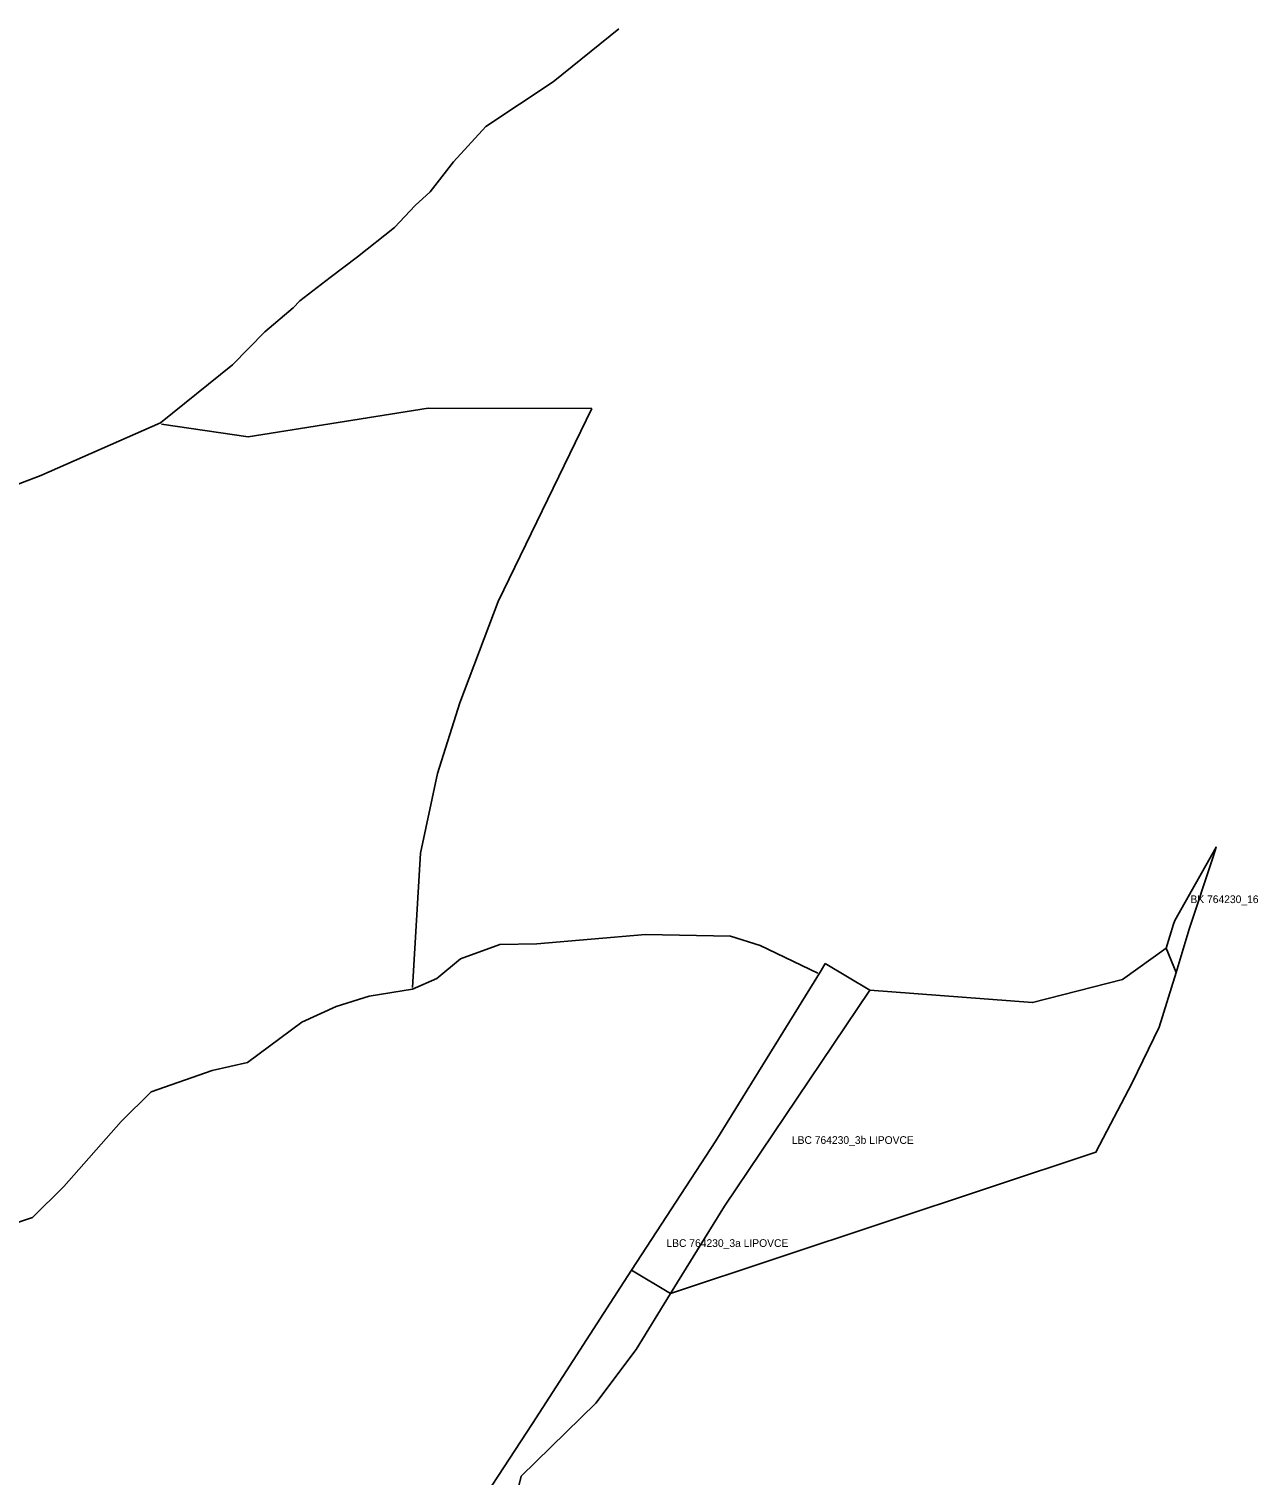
# Model space of a CAD drawing. Extents: x -521616 to -516782, y -1190061 to -1184927.
# Drawn here: x -517900 to -516782, y -1187423 to -1186108 of the extents above; entities that cross this region are included whole.
import ezdxf

# ---------------------------------------------------------------- set-up
doc = ezdxf.new("R2010")
doc.units = 0
for name, color, linetype in [('i_prvek_l_n', 7, 'Continuous'), ('i_prvek_l_s', 7, 'Continuous'), ('LBC_n', 7, 'Continuous'), ('LBC_s', 7, 'Continuous'), ('LBK_s', 7, 'Continuous')]:
    doc.layers.add(name, color=color, linetype=linetype)

msp = doc.modelspace()

# ---------------------------------------------------------------- linework, layer by layer
at = {"layer": 'i_prvek_l_n'}
for points in [[(-517567.3, -1186288.9), (-517548.4, -1186268.9), (-517534.7, -1186256.5), (-517513.6, -1186229.1), (-517484.3, -1186196.9), (-517422.9, -1186156.3), (-517363.2, -1186108.3)], [(-517551, -1186980.2), (-517543.5, -1186858), (-517528.2, -1186785.5), (-517507.7, -1186721.1), (-517472.9, -1186629), (-517387.7, -1186453.4)], [(-517182.2, -1186967.1), (-517234.6, -1186941.8), (-517261.6, -1186933.5), (-517338.9, -1186931.9), (-517437.7, -1186940.4), (-517471.4, -1186941.1)]]:
    msp.add_lwpolyline(points, dxfattribs=at)
at = {"layer": 'i_prvek_l_s'}
for points in [[(-518041.6, -1186572.7), (-517888.9, -1186514.4), (-517779.9, -1186466.6), (-517714.7, -1186413.9), (-517685.2, -1186383.8), (-517659.5, -1186362), (-517653.4, -1186355.5), (-517625.7, -1186334.2), (-517600.9, -1186315.4), (-517567.3, -1186288.9)], [(-517387.7, -1186453.4), (-517536.6, -1186453.3), (-517700.2, -1186479.2), (-517779.2, -1186467.7)], [(-517471.4, -1186941.1), (-517507.3, -1186954), (-517528.6, -1186972), (-517550.9, -1186981.5), (-517590.4, -1186987.8), (-517620.4, -1186997.2), (-517651.4, -1187011.5), (-517701, -1187048.2), (-517732.9, -1187055.4), (-517788.4, -1187074.8), (-517815.9, -1187101.9), (-517868, -1187160.9), (-517896.4, -1187189.1), (-517919.8, -1187197.1)]]:
    msp.add_lwpolyline(points, dxfattribs=at)
at = {"layer": 'LBC_n'}
msp.add_lwpolyline([(-517134.9, -1186982.4), (-516987, -1186993.8), (-516905.3, -1186972.8), (-516865.5, -1186944.2), (-516856.6, -1186966.5), (-516871.9, -1187016.2), (-516896.6, -1187066.8), (-516929.4, -1187129.9), (-517316.2, -1187258.5), (-517267.2, -1187178.8), (-517201, -1187080.6)], close=True, dxfattribs=at)
at = {"layer": 'LBC_s'}
msp.add_lwpolyline([(-517175.5, -1186958.2), (-517134.9, -1186982.4), (-517201, -1187080.6), (-517267.2, -1187178.8), (-517316.2, -1187258.5), (-517351.7, -1187237.2), (-517275.2, -1187119.6), (-517179.4, -1186964.6)], close=True, dxfattribs=at)
at = {"layer": 'LBK_s'}
for points in [[(-516865.5, -1186944.2), (-516858.9, -1186922.6), (-516857.7, -1186919), (-516820.2, -1186852.3), (-516822.8, -1186861.2), (-516844.6, -1186927.1), (-516856.6, -1186966.5)], [(-517585.7, -1187655.1), (-517522.9, -1187523.6), (-517517, -1187506.5), (-517509.9, -1187480.8), (-517441.7, -1187376.6), (-517361.8, -1187252.7), (-517351.7, -1187237.2), (-517316.2, -1187258.5), (-517347.4, -1187309.2), (-517384.1, -1187358), (-517452.1, -1187424.5), (-517463.8, -1187472.2), (-517476, -1187504.6), (-517514.9, -1187575.8), (-517537.2, -1187601.4), (-517569.9, -1187660.8), (-517578.6, -1187659.3), (-517585.7, -1187655.1)]]:
    msp.add_lwpolyline(points, close=True, dxfattribs=at)

# ---------------------------------------------------------------- texts
at = {"layer": 'LBC_n'}
msp.add_text('LBC 764230_3b LIPOVCE', height=7, dxfattribs=at).set_placement((-517205.9, -1187122.3))
at = {"layer": 'LBC_s'}
msp.add_text('LBC 764230_3a LIPOVCE', height=7, dxfattribs=at).set_placement((-517320, -1187216))
at = {"layer": 'LBK_s'}
msp.add_text('BK 764230_16', height=7, dxfattribs=at).set_placement((-516843.5, -1186903.3))

doc.saveas('drawing.dxf')
